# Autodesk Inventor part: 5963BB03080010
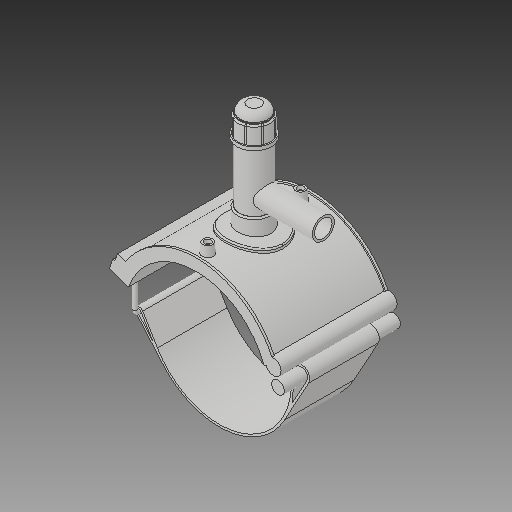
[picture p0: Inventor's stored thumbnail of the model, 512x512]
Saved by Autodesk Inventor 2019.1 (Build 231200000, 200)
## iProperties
Created: 2017-07
Part Number: 5963BB03080010
Material: Generic
Description: PLASSON TAPPING SADDLE 8''IPS x 1''IPS
Document SubType Name: Modeling
Designer: KIM
Mass: 1712.7 g
Surface Area: 2671.49 cm^2
Volume: 1712.7 cm^3
Density: 1 g/cm^3
Appearance: Default
Author: KIM
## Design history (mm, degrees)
derived "5963B.ipt"
feature "Solid1::5963B.ipt"
feature "Solid2::5963B.ipt"
feature "Solid4::5963B.ipt"
feature "Solid5::5963B.ipt"
tag "TaggingFeature1" dims "d0" = 218.7
body "Solid1"
body "Solid2"
other parameters: "d2" = 269.748, "d3" = 54.675, "d4" = 176.022, "d5" = 0, "d6" = 0.1, "d8" = 0, "d19" = 6, "d20" = 6, "d21" = 105.6132, "d23" = 0, "d24" = 52.8066, "d26" = 0, "d29" = 3, "d30" = 72.9, "d31" = 6, "d32" = 0, "d33" = 0, "d34" = 0.6, "d40" = 129.64536, "d41" = 87.48, "d43" = 0, "d45" = 0, "d47" = 230.2722, "d70" = 15, "d72" = 0, "d73" = 6, "d75" = 5, "d76" = 0, "d77" = 10.935, "d78" = 139.35, "d79" = 15, "d80" = 70.4088, "d82" = 5 deg, "d84" = 4, "d85" = 14, "d86" = 0, "d87" = 3, "d88" = 0, "d89" = 1, "d90" = 1, "d91" = 140.8176, "d92" = 0, "d93" = 0.5, "d94" = 115.10526, "d96" = 254.30436, "d97" = 3.52044, "d98" = 0, "d102" = 2.187, "d120" = 140 deg, "d121" = 24.228, "d122" = 20 deg, "d123" = 498.636, "d124" = 149.5908, "d126" = 0, "d143" = 225.261, "d145" = 23.55231, "d149" = 3.2805, "d150" = 25.90754, "d153" = 176.022, "d154" = 0, "d156" = 124.659, "d157" = 160 deg, "d159" = 6.1236, "d161" = 3.2805, "d162" = 105.6132, "d163" = 0, "d164" = 109.35, "d167" = 21.87, "d168" = 121.61854, "d170" = 3.2805, "d172" = 0, "d173" = 1, "d175" = 109.35, "d176" = 20 deg, "d177" = 15.309, "d178" = 30.618, "d180" = 0, "d183" = 12.2472, "d184" = 12.2472, "d185" = 57.20715, "d186" = 57.20715, "d187" = 124.659, "d188" = 9.1854, "d189" = 15.309, "d190" = 0, "d191" = 186.9885, "d193" = 6.1236, "d194" = 6.16077, "d195" = 90 deg, "d197" = 0, "d199" = 0, "d200" = 15.309, "d202" = 0, "d203" = 177.038, "d204" = 49.8636, "d205" = 36.7416, "d206" = 44.6148, "d207" = 132.7785, "d208" = 138.08964, "d209" = 164.64534, "d210" = 45.13968, "d211" = 52.488, "d212" = 41.9904, "d213" = 43.5366, "d216" = 0, "d217" = 21.87, "d218" = 10.935, "d219" = 2.187, "d222" = 218.7, "d224" = 0, "d230" = 2.187, "d233" = 6, "d236" = 89.916, "d237" = 52.8066, "d238" = 6.02433, "d240" = 52.8066, "d241" = 52.8066, "d242" = 52.8066, "d243" = 6, "d244" = 52.8066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
